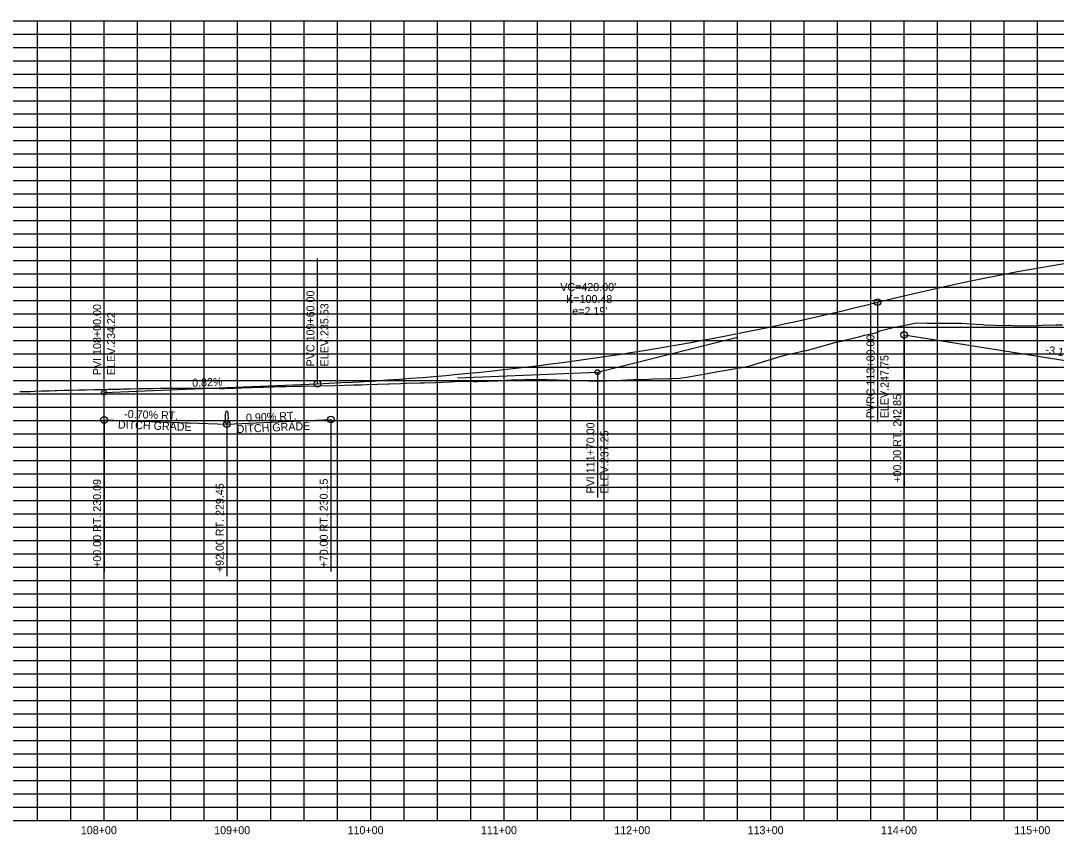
# Model space of a CAD drawing. Extents: x 921603 to 924670, y 1759276 to 1766491.
# Drawn here: x 922377 to 923154, y 1764922 to 1765532 of the extents above; entities that cross this region are included whole.
import ezdxf

# ---------------------------------------------------------------- set-up
doc = ezdxf.new("R2010")
doc.units = 0
for name, color, linetype in [('R_Axis_Annotation', 7, 'Continuous'), ('R_Drainage', 7, 'Continuous'), ('R_Exist Surface', 7, 'Continuous'), ('R_Grid', 7, 'Continuous'), ('R_Grid_Minor', 7, 'Continuous'), ('R_Vert Alg', 7, 'Continuous'), ('R_Vert Alg Annot', 7, 'Continuous')]:
    doc.layers.add(name, color=color, linetype=linetype)

msp = doc.modelspace()

# ---------------------------------------------------------------- linework, layer by layer
at = {"layer": 'R_Drainage'}
msp.add_ellipse((922531.83, 1765234.51), major_axis=(0, 5), ratio=0.2, dxfattribs=at)
at = {"layer": 'R_Exist Surface'}
msp.add_lwpolyline([(922376.57, 1765254.09), (922382.12, 1765254.12), (922384.02, 1765254.13), (922384.44, 1765254.14), (922384.76, 1765254.15), (922387.66, 1765254.26), (922393.21, 1765254.46), (922398.76, 1765254.64), (922403.24, 1765254.78), (922404.3, 1765254.81), (922409.85, 1765254.96), (922415.4, 1765255.1), (922416.28, 1765255.12), (922420.94, 1765255.21), (922421.79, 1765255.23), (922422.05, 1765255.23), (922426.49, 1765255.36), (922432.04, 1765255.51), (922436.99, 1765255.62), (922437.08, 1765255.63), (922437.58, 1765255.64), (922443.13, 1765255.75), (922448.68, 1765255.84), (922451.81, 1765255.89), (922452.13, 1765255.9), (922454.22, 1765255.95), (922459.77, 1765256.08), (922465.32, 1765256.19), (922468.82, 1765256.25), (922468.97, 1765256.26), (922469.12, 1765256.27), (922470.86, 1765256.3), (922476.41, 1765256.38), (922481.96, 1765256.45), (922485.81, 1765256.5), (922486.25, 1765256.51), (922487.5, 1765256.52), (922493.05, 1765256.54), (922498.6, 1765256.55), (922502.46, 1765256.55), (922502.76, 1765256.56), (922504.14, 1765256.56), (922509.69, 1765256.55), (922515.24, 1765256.54), (922519.1, 1765256.52), (922519.5, 1765256.53), (922520.78, 1765256.5), (922526.33, 1765256.39), (922528.84, 1765256.33), (922530.11, 1765256.41), (922531.88, 1765256.47), (922537.42, 1765256.65), (922542.97, 1765256.82), (922548.02, 1765256.97), (922548.52, 1765257), (922550.13, 1765257.1), (922554.06, 1765257.22), (922559.61, 1765257.39), (922565.16, 1765257.55), (922566.96, 1765257.61), (922570.7, 1765257.7), (922572.44, 1765257.75), (922576.25, 1765257.82), (922581.8, 1765257.93), (922587.34, 1765258.04), (922589.64, 1765258.08), (922601.07, 1765258.37), (922612.88, 1765258.6), (922626.94, 1765259), (922632.76, 1765259.16), (922636.96, 1765259.28), (922652.78, 1765259.72), (922653.82, 1765259.75), (922662.45, 1765260.1), (922665.7, 1765260.2), (922666.35, 1765260.2), (922677.04, 1765260.48), (922679.88, 1765260.49), (922688.33, 1765260.83), (922693.04, 1765261.07), (922699.4, 1765261.33), (922706.23, 1765261.69), (922717.2, 1765261.53), (922719.76, 1765261.57), (922727.46, 1765261.78), (922733.33, 1765261.97), (922735.07, 1765261.99), (922745.24, 1765262.75), (922755.46, 1765263.05), (922770.25, 1765262.96), (922771.49, 1765262.97), (922772.11, 1765262.97), (922787.46, 1765262.58), (922790.73, 1765262.43), (922803.07, 1765262.07), (922809.23, 1765261.77), (922816.01, 1765262.02), (922823.38, 1765262.39), (922832.2, 1765262.69), (922837.48, 1765262.95), (922842.03, 1765263.09), (922848.38, 1765263.29), (922851.52, 1765263.44), (922863.53, 1765263.8), (922864.56, 1765263.83), (922865.51, 1765263.88), (922871.52, 1765264.05), (922878.03, 1765265.11), (922879.58, 1765265.39), (922885.03, 1765266.29), (922889.55, 1765267.03), (922893.71, 1765267.8), (922900.02, 1765268.95), (922906.53, 1765270.07), (922907.8, 1765270.29), (922917.74, 1765272.13), (922921.84, 1765272.85), (922925.77, 1765273.79), (922928.03, 1765274.5), (922945.2, 1765279.9), (922949.53, 1765281.02), (922951.46, 1765281.51), (922964.83, 1765284.49), (922967.95, 1765285.11), (922969.05, 1765285.64), (922971.03, 1765286.18), (922988.77, 1765291), (922992.54, 1765291.84), (922996.43, 1765292.71), (923006.9, 1765295.42), (923010.09, 1765296.32), (923014.04, 1765297.08), (923018.56, 1765297.95), (923021.54, 1765299.67), (923021.55, 1765299.67), (923031.52, 1765302.16), (923035.54, 1765302.92), (923049.29, 1765305.53), (923057.04, 1765305.42), (923073.82, 1765305.2), (923078.54, 1765305.25), (923078.89, 1765305.26), (923082.88, 1765305.37), (923082.96, 1765305.37), (923093.7, 1765304.61), (923098.68, 1765304.21), (923100.04, 1765304.16), (923115.96, 1765303.62), (923117.7, 1765303.78), (923121.55, 1765303.69), (923136.84, 1765303.36), (923140.28, 1765303.64), (923143.05, 1765303.74), (923143.18, 1765303.74), (923153.87, 1765303.95), (923158.57, 1765304.12)], dxfattribs=at)
at = {"layer": 'R_Grid'}
for p, q in [((921639.83, 1765532.26), (924639.83, 1765532.26)), ((921639.83, 1765532.26), (924639.83, 1765532.26)), ((922439.83, 1764932.26), (922439.83, 1765532.26)), ((922539.83, 1764932.26), (922539.83, 1765532.26)), ((922639.83, 1764932.26), (922639.83, 1765532.26)), ((922739.83, 1764932.26), (922739.83, 1765532.26)), ((922839.83, 1764932.26), (922839.83, 1765532.26)), ((922939.83, 1764932.26), (922939.83, 1765532.26)), ((923039.83, 1764932.26), (923039.83, 1765532.26)), ((923139.83, 1764932.26), (923139.83, 1765532.26)), ((921639.83, 1765482.26), (924639.83, 1765482.26)), ((921639.83, 1765432.26), (924639.83, 1765432.26)), ((921639.83, 1765382.26), (924639.83, 1765382.26)), ((921639.83, 1765332.26), (924639.83, 1765332.26)), ((921639.83, 1765282.26), (924639.83, 1765282.26)), ((921639.83, 1765232.26), (924639.83, 1765232.26)), ((921639.83, 1765182.26), (924639.83, 1765182.26)), ((921639.83, 1765132.26), (924639.83, 1765132.26)), ((921639.83, 1765082.26), (924639.83, 1765082.26)), ((921639.83, 1765032.26), (924639.83, 1765032.26)), ((921639.83, 1764982.26), (924639.83, 1764982.26)), ((921639.83, 1764932.26), (924639.83, 1764932.26))]:
    msp.add_line(p, q, dxfattribs=at)
at = {"layer": 'R_Grid_Minor'}
for p, q in [((922389.83, 1764932.26), (922389.83, 1765532.26)), ((922414.83, 1764932.26), (922414.83, 1765532.26)), ((922464.83, 1764932.26), (922464.83, 1765532.26)), ((922489.83, 1764932.26), (922489.83, 1765532.26)), ((922514.83, 1764932.26), (922514.83, 1765532.26)), ((922564.83, 1764932.26), (922564.83, 1765532.26)), ((922589.83, 1764932.26), (922589.83, 1765532.26)), ((922614.83, 1764932.26), (922614.83, 1765532.26)), ((922664.83, 1764932.26), (922664.83, 1765532.26)), ((922689.83, 1764932.26), (922689.83, 1765532.26)), ((922714.83, 1764932.26), (922714.83, 1765532.26)), ((922764.83, 1764932.26), (922764.83, 1765532.26)), ((922789.83, 1764932.26), (922789.83, 1765532.26)), ((922814.83, 1764932.26), (922814.83, 1765532.26)), ((922864.83, 1764932.26), (922864.83, 1765532.26)), ((922889.83, 1764932.26), (922889.83, 1765532.26)), ((922914.83, 1764932.26), (922914.83, 1765532.26)), ((922964.83, 1764932.26), (922964.83, 1765532.26)), ((922989.83, 1764932.26), (922989.83, 1765532.26)), ((923014.83, 1764932.26), (923014.83, 1765532.26)), ((923064.83, 1764932.26), (923064.83, 1765532.26)), ((923089.83, 1764932.26), (923089.83, 1765532.26)), ((923114.83, 1764932.26), (923114.83, 1765532.26)), ((921639.83, 1765522.26), (924639.83, 1765522.26)), ((921639.83, 1765512.26), (924639.83, 1765512.26)), ((921639.83, 1765502.26), (924639.83, 1765502.26)), ((921639.83, 1765492.26), (924639.83, 1765492.26)), ((921639.83, 1765472.26), (924639.83, 1765472.26)), ((921639.83, 1765462.26), (924639.83, 1765462.26)), ((921639.83, 1765452.26), (924639.83, 1765452.26)), ((921639.83, 1765442.26), (924639.83, 1765442.26)), ((921639.83, 1765422.26), (924639.83, 1765422.26)), ((921639.83, 1765412.26), (924639.83, 1765412.26)), ((921639.83, 1765402.26), (924639.83, 1765402.26)), ((921639.83, 1765392.26), (924639.83, 1765392.26)), ((921639.83, 1765372.26), (924639.83, 1765372.26)), ((921639.83, 1765362.26), (924639.83, 1765362.26)), ((921639.83, 1765352.26), (924639.83, 1765352.26)), ((921639.83, 1765342.26), (924639.83, 1765342.26)), ((921639.83, 1765322.26), (924639.83, 1765322.26)), ((921639.83, 1765312.26), (924639.83, 1765312.26)), ((921639.83, 1765302.26), (924639.83, 1765302.26)), ((921639.83, 1765292.26), (924639.83, 1765292.26)), ((921639.83, 1765272.26), (924639.83, 1765272.26)), ((921639.83, 1765262.26), (924639.83, 1765262.26)), ((921639.83, 1765252.26), (924639.83, 1765252.26)), ((921639.83, 1765242.26), (924639.83, 1765242.26)), ((921639.83, 1765222.26), (924639.83, 1765222.26)), ((921639.83, 1765212.26), (924639.83, 1765212.26)), ((921639.83, 1765202.26), (924639.83, 1765202.26)), ((921639.83, 1765192.26), (924639.83, 1765192.26)), ((921639.83, 1765172.26), (924639.83, 1765172.26)), ((921639.83, 1765162.26), (924639.83, 1765162.26)), ((921639.83, 1765152.26), (924639.83, 1765152.26)), ((921639.83, 1765142.26), (924639.83, 1765142.26)), ((921639.83, 1765122.26), (924639.83, 1765122.26)), ((921639.83, 1765112.26), (924639.83, 1765112.26)), ((921639.83, 1765102.26), (924639.83, 1765102.26)), ((921639.83, 1765092.26), (924639.83, 1765092.26)), ((921639.83, 1765072.26), (924639.83, 1765072.26)), ((921639.83, 1765062.26), (924639.83, 1765062.26)), ((921639.83, 1765052.26), (924639.83, 1765052.26)), ((921639.83, 1765042.26), (924639.83, 1765042.26)), ((921639.83, 1765022.26), (924639.83, 1765022.26)), ((921639.83, 1765012.26), (924639.83, 1765012.26)), ((921639.83, 1765002.26), (924639.83, 1765002.26)), ((921639.83, 1764992.26), (924639.83, 1764992.26)), ((921639.83, 1764972.26), (924639.83, 1764972.26)), ((921639.83, 1764962.26), (924639.83, 1764962.26)), ((921639.83, 1764952.26), (924639.83, 1764952.26)), ((921639.83, 1764942.26), (924639.83, 1764942.26))]:
    msp.add_line(p, q, dxfattribs=at)
at = {"layer": 'R_Vert Alg'}
for p, q in [((923039.83, 1765296.51), (923354.83, 1765246.21)), ((922439.83, 1765253.34), (922599.83, 1765259.9)), ((922439.83, 1765232.71), (922531.83, 1765229.51)), ((922531.83, 1765229.51), (922609.83, 1765233.01))]:
    msp.add_line(p, q, dxfattribs=at)
for points in [[(923019.83, 1765321.01), (923037.33, 1765325.29), (923054.83, 1765329.39), (923072.33, 1765333.31), (923089.83, 1765337.05), (923107.33, 1765340.61), (923124.83, 1765343.98), (923142.33, 1765347.17), (923159.83, 1765350.18)], [(922599.83, 1765259.9), (922608.58, 1765260.28), (922617.33, 1765260.69), (922626.08, 1765261.15), (922634.83, 1765261.64), (922643.58, 1765262.17), (922652.33, 1765262.74), (922661.08, 1765263.34), (922669.83, 1765263.99), (922678.58, 1765264.67), (922687.33, 1765265.39), (922696.08, 1765266.15), (922704.83, 1765266.95), (922713.58, 1765267.78), (922722.33, 1765268.66), (922731.08, 1765269.57), (922739.83, 1765270.52), (922748.58, 1765271.5), (922757.33, 1765272.53), (922766.08, 1765273.59), (922774.83, 1765274.69), (922783.58, 1765275.83), (922792.33, 1765277.01), (922801.08, 1765278.23), (922818.58, 1765280.77), (922827.33, 1765282.1), (922836.08, 1765283.47), (922844.83, 1765284.88), (922853.58, 1765286.32), (922862.33, 1765287.81), (922871.08, 1765289.33), (922879.83, 1765290.89), (922888.58, 1765292.48), (922897.33, 1765294.12), (922906.08, 1765295.79), (922914.83, 1765297.5), (922923.58, 1765299.25), (922932.33, 1765301.04), (922941.08, 1765302.87), (922949.83, 1765304.73), (922958.58, 1765306.63), (922967.33, 1765308.57), (922976.08, 1765310.55), (922984.83, 1765312.56), (922993.58, 1765314.62), (923002.33, 1765316.71), (923011.08, 1765318.84), (923019.83, 1765321.01)]]:
    msp.add_lwpolyline(points, dxfattribs=at)
at = {"layer": 'R_Vert Alg Annot'}
for p, q in [((922599.83, 1765269.9), (922599.83, 1765353.9)), ((922439.83, 1765263.34), (922439.83, 1765347.34)), ((923019.83, 1765321.01), (923019.83, 1765231.01)), ((922809.83, 1765268.51), (922914.83, 1765294.76)), ((923039.83, 1765296.51), (923039.83, 1765266.51)), ((922599.83, 1765259.9), (922599.83, 1765269.9)), ((922704.83, 1765264.2), (922809.83, 1765268.51)), ((922809.83, 1765268.51), (922809.83, 1765258.51)), ((922439.83, 1765253.34), (922439.83, 1765263.34)), ((923039.83, 1765266.51), (923039.83, 1765182.51)), ((922809.83, 1765258.51), (922809.83, 1765174.51)), ((922439.83, 1765232.71), (922439.83, 1765202.71)), ((922531.83, 1765229.51), (922531.83, 1765199.51)), ((922531.83, 1765229.51), (922531.83, 1765199.51)), ((922609.83, 1765233.01), (922609.83, 1765203.01)), ((922439.83, 1765202.71), (922439.83, 1765118.71)), ((922531.83, 1765199.51), (922531.83, 1765115.51)), ((922531.83, 1765199.51), (922531.83, 1765115.51)), ((922609.83, 1765203.01), (922609.83, 1765119.01))]:
    msp.add_line(p, q, dxfattribs=at)
for centre, radius in [((923019.83, 1765321.01), 2.5), ((923039.83, 1765296.51), 2.5), ((922809.83, 1765268.51), 1.85), ((922599.83, 1765259.9), 2.5), ((922439.83, 1765253.34), 1.85), ((922439.83, 1765232.71), 2.5), ((922531.83, 1765229.51), 2.5), ((922531.83, 1765229.51), 2.5), ((922609.83, 1765233.01), 2.5)]:
    msp.add_circle(centre, radius, dxfattribs=at)

# ---------------------------------------------------------------- texts
at = {"layer": 'R_Axis_Annotation'}
for s, p in [('108+00', (922422.42, 1764921.91)), ('109+00', (922522.42, 1764921.91)), ('110+00', (922622.42, 1764921.91)), ('111+00', (922722.42, 1764921.91)), ('112+00', (922822.42, 1764921.91)), ('113+00', (922922.42, 1764921.91)), ('114+00', (923022.42, 1764921.91)), ('115+00', (923122.42, 1764921.91))]:
    msp.add_text(s, height=6, dxfattribs=at).set_placement(p)
at = {"layer": 'R_Vert Alg Annot'}
for s, rotation, p in [('PVC 109+60.00', 90, (922597.58, 1765272.9)), ('PVI 108+00.00', 90, (922437.58, 1765266.34)), ('ELEV.235.53', 90, (922608.08, 1765272.9)), ('ELEV.234.22', 90, (922448.08, 1765266.34)), ('PVRC 113+80.00', 90, (923017.58, 1765234.01)), ('-3.19% RT. DITCH GRADE', 350.92746, (923145.43, 1765282.66)), ('ELEV.247.75', 90, (923028.08, 1765234.01)), ('0.82%', 2.34781, (922505.98, 1765257.55)), ('+00.00 RT. 242.85', 90, (923037.58, 1765185.51)), ('-0.70% RT. ', 358.00791, (922454.83, 1765234.31)), ('0.90% RT. ', 2.56924, (922546.41, 1765231.3)), ('DITCH GRADE', 358.00791, (922450.17, 1765226.34)), ('DITCH GRADE', 2.56924, (922539.4, 1765222.85)), ('PVI 111+70.00', 90, (922807.58, 1765177.51)), ('ELEV.237.25', 90, (922818.08, 1765177.51)), ('+00.00 RT. 230.09', 90, (922437.58, 1765121.71)), ('+92.00 RT. 229.45', 90, (922529.58, 1765118.51)), ('+92.00 RT. 229.45', 90, (922529.58, 1765118.51)), ('+70.00 RT. 230.15', 90, (922607.58, 1765122.01))]:
    msp.add_text(s, height=6, rotation=rotation, dxfattribs=at).set_placement(p)
for s, p in [("VC=420.00'", (922781.93, 1765329.4)), ('K=100.48', (922786.35, 1765320.4)), ("e=2.19'", (922790.93, 1765311.4))]:
    msp.add_text(s, height=6, dxfattribs=at).set_placement(p)

doc.saveas('drawing.dxf')
